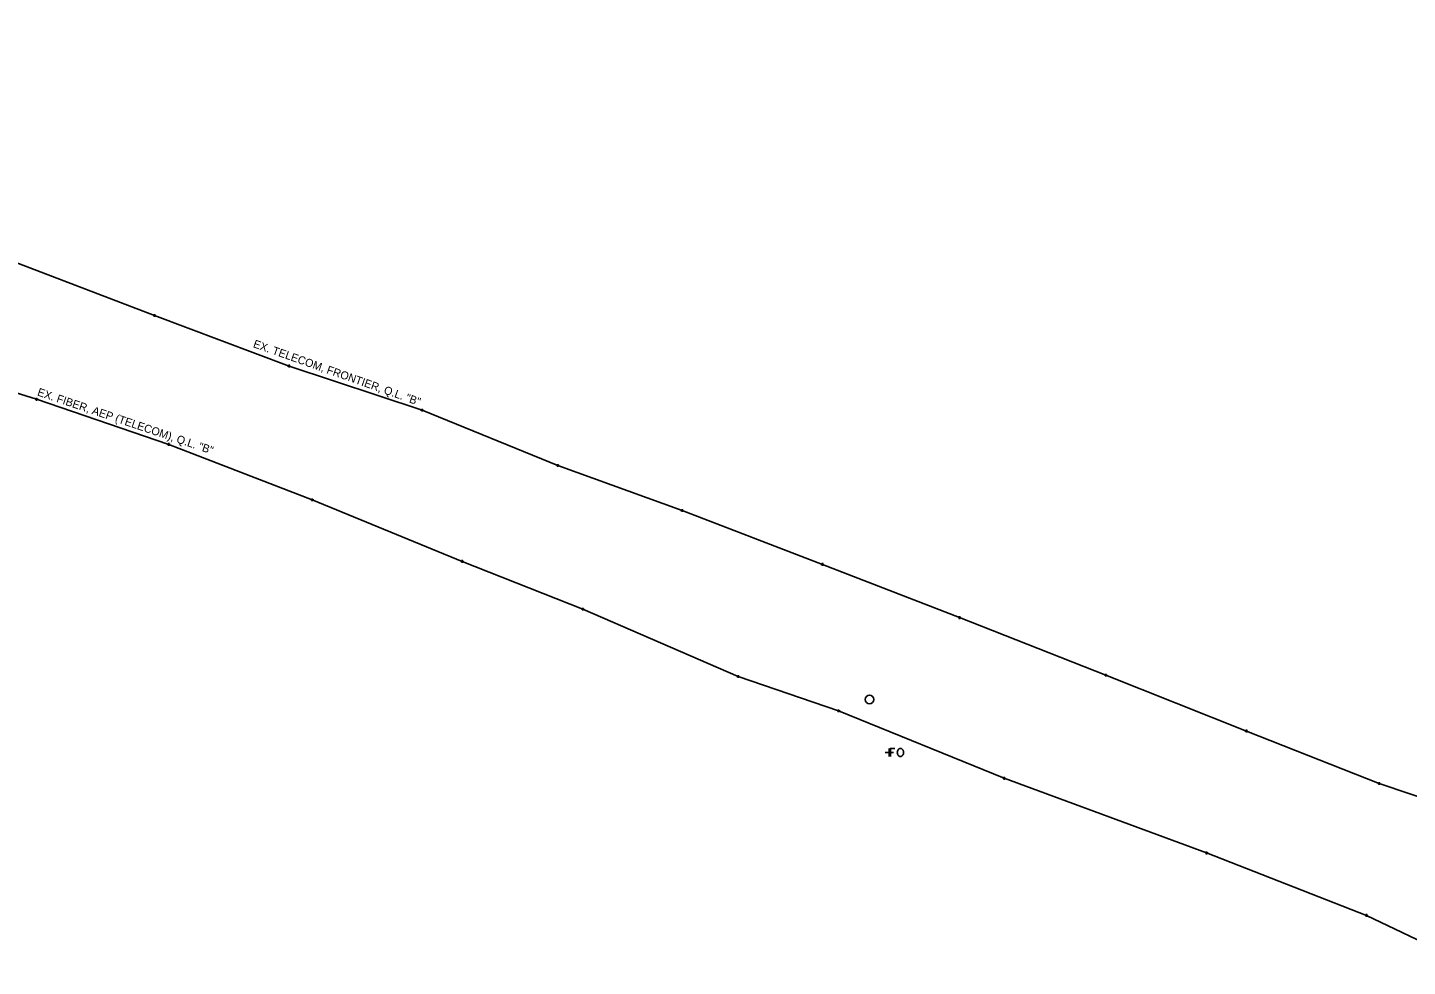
# Model space of a CAD drawing. Extents: x 2046588 to 2048646, y 455919 to 457871.
# Drawn here: x 2047066.7 to 2047549.4, y 456989.8 to 457318.3 of the extents above; entities that cross this region are included whole.
import ezdxf

# ---------------------------------------------------------------- set-up
doc = ezdxf.new("R2010")
doc.units = 0
for name, color, linetype in [('CM_Corridor_Top_Mesh', 7, 'Continuous'), ('MD_P_Surface_Non-Reinforced_Concrete_Pavement', 7, 'Continuous'), ('UT_X_Gas', 7, 'Continuous'), ('UT_X_Gas_Text', 7, 'Continuous'), ('UT_X_Overhead_Combined', 7, 'Continuous'), ('UT_X_Telecom_Text', 7, 'Continuous')]:
    doc.layers.add(name, color=color, linetype=linetype)

msp = doc.modelspace()

# ---------------------------------------------------------------- linework, layer by layer
at = {"layer": 'CM_Corridor_Top_Mesh'}
msp.add_lwpolyline([(2046591.62, 457318.3), (2046634.49, 457314.33), (2046683.6, 457309.26), (2046728.87, 457304.51), (2046756.52, 457301.8), (2046770.98, 457300.11), (2046793.5, 457299.64), (2046823.77, 457296.38), (2046919.05, 457278.1), (2046970.54, 457267.22), (2047006.64, 457256.03), (2047063.52, 457235.76), (2047111.08, 457217.54), (2047158.16, 457199.88), (2047204.68, 457184.45), (2047252.22, 457165.07), (2047295.66, 457149.33), (2047344.75, 457130.49), (2047392.72, 457111.85), (2047443.95, 457091.74), (2047493.09, 457072.16), (2047539.56, 457053.79), (2047583.55, 457039.04), (2047596.82, 457037.26)], dxfattribs=at)
at = {"layer": 'UT_X_Gas'}
for p, q in [((2047110.58, 457217.54), (2047111.58, 457217.54)), ((2047111.08, 457218.04), (2047111.08, 457217.04)), ((2047111.08, 457217.54), (2047111.08, 457217.54)), ((2047157.66, 457199.88), (2047158.66, 457199.88)), ((2047158.16, 457200.38), (2047158.16, 457199.38)), ((2047158.16, 457199.88), (2047158.16, 457199.88)), ((2047069.35, 457188.24), (2047070.35, 457188.24)), ((2047069.85, 457188.74), (2047069.85, 457187.74)), ((2047069.85, 457188.24), (2047069.85, 457188.24)), ((2047204.18, 457184.45), (2047205.18, 457184.45)), ((2047204.68, 457184.95), (2047204.68, 457183.95)), ((2047204.68, 457184.45), (2047204.68, 457184.45)), ((2047115.55, 457172.46), (2047116.55, 457172.46)), ((2047116.05, 457172.96), (2047116.05, 457171.96)), ((2047116.05, 457172.46), (2047116.05, 457172.46)), ((2047252.22, 457165.57), (2047252.22, 457164.57)), ((2047251.72, 457165.07), (2047252.72, 457165.07)), ((2047252.22, 457165.07), (2047252.22, 457165.07)), ((2047165.8, 457153.05), (2047166.8, 457153.05)), ((2047166.3, 457153.55), (2047166.3, 457152.55)), ((2047166.3, 457153.05), (2047166.3, 457153.05)), ((2047295.16, 457149.33), (2047296.16, 457149.33)), ((2047295.66, 457149.83), (2047295.66, 457148.83)), ((2047295.66, 457149.33), (2047295.66, 457149.33)), ((2047218.25, 457131.54), (2047219.25, 457131.54)), ((2047218.75, 457132.04), (2047218.75, 457131.04)), ((2047218.75, 457131.54), (2047218.75, 457131.54)), ((2047344.25, 457130.49), (2047345.25, 457130.49)), ((2047344.75, 457130.99), (2047344.75, 457129.99)), ((2047344.75, 457130.49), (2047344.75, 457130.49)), ((2047260.44, 457114.81), (2047261.44, 457114.81)), ((2047260.94, 457115.31), (2047260.94, 457114.31)), ((2047260.94, 457114.81), (2047260.94, 457114.81)), ((2047392.72, 457112.35), (2047392.72, 457111.35)), ((2047392.22, 457111.85), (2047393.22, 457111.85)), ((2047392.72, 457111.85), (2047392.72, 457111.85)), ((2047314.78, 457091.24), (2047315.78, 457091.24)), ((2047315.28, 457091.74), (2047315.28, 457090.74)), ((2047315.28, 457091.24), (2047315.28, 457091.24)), ((2047443.45, 457091.74), (2047444.45, 457091.74)), ((2047443.95, 457092.24), (2047443.95, 457091.24)), ((2047443.95, 457091.74), (2047443.95, 457091.74)), ((2047349.92, 457079.24), (2047350.92, 457079.24)), ((2047350.42, 457079.74), (2047350.42, 457078.74)), ((2047350.42, 457079.24), (2047350.42, 457079.24)), ((2047492.59, 457072.16), (2047493.59, 457072.16)), ((2047493.09, 457072.66), (2047493.09, 457071.66)), ((2047493.09, 457072.16), (2047493.09, 457072.16)), ((2047407.85, 457055.65), (2047408.85, 457055.65)), ((2047408.35, 457056.15), (2047408.35, 457055.15)), ((2047408.35, 457055.65), (2047408.35, 457055.65)), ((2047539.56, 457054.29), (2047539.56, 457053.29)), ((2047539.06, 457053.79), (2047540.06, 457053.79)), ((2047539.56, 457053.79), (2047539.56, 457053.79)), ((2047479.2, 457030.01), (2047479.2, 457029.01)), ((2047478.7, 457029.51), (2047479.7, 457029.51)), ((2047479.2, 457029.51), (2047479.2, 457029.51)), ((2047534.64, 457007.65), (2047535.64, 457007.65)), ((2047535.14, 457008.15), (2047535.14, 457007.15)), ((2047535.14, 457007.65), (2047535.14, 457007.65))]:
    msp.add_line(p, q, dxfattribs=at)
at = {"layer": 'UT_X_Gas_Text'}
for p, q in [((2047368.15, 457064.67), (2047366.75, 457064.67)), ((2047368.15, 457066.07), (2047368.15, 457063.27)), ((2047368.55, 457064.7), (2047369.63, 457064.7))]:
    msp.add_line(p, q, dxfattribs=at)
for points in [[(2047370.07, 457066.07), (2047368.55, 457066.07), (2047368.55, 457063.27)], [(2047371.84, 457066.05), (2047371.77, 457066.03), (2047371.7, 457066), (2047371.59, 457065.94), (2047371.53, 457065.89), (2047371.42, 457065.81), (2047371.33, 457065.72), (2047371.28, 457065.67), (2047371.22, 457065.59), (2047371.11, 457065.36), (2047371.02, 457065.14), (2047370.98, 457064.95), (2047370.95, 457064.66), (2047370.98, 457064.35), (2047371.04, 457064.13), (2047371.11, 457063.95), (2047371.15, 457063.87), (2047371.22, 457063.76), (2047371.31, 457063.65), (2047371.37, 457063.58), (2047371.44, 457063.51), (2047371.53, 457063.45), (2047371.64, 457063.38), (2047371.84, 457063.29), (2047371.95, 457063.27), (2047372.17, 457063.27), (2047372.25, 457063.29), (2047372.34, 457063.31), (2047372.45, 457063.36), (2047372.56, 457063.42), (2047372.63, 457063.47), (2047372.69, 457063.51), (2047372.76, 457063.58), (2047372.83, 457063.67), (2047372.87, 457063.73), (2047372.92, 457063.8), (2047372.96, 457063.87), (2047373.03, 457064), (2047373.09, 457064.15), (2047373.14, 457064.33), (2047373.16, 457064.48), (2047373.16, 457064.51), (2047373.16, 457064.66), (2047373.16, 457064.79), (2047373.14, 457064.97), (2047373.09, 457065.14), (2047373.05, 457065.28), (2047372.98, 457065.43), (2047372.92, 457065.56), (2047372.81, 457065.7), (2047372.72, 457065.78), (2047372.63, 457065.87), (2047372.54, 457065.94), (2047372.41, 457066), (2047372.28, 457066.05), (2047372.14, 457066.07), (2047371.99, 457066.07), (2047371.84, 457066.05)]]:
    msp.add_lwpolyline(points, dxfattribs=at)
at = {"layer": 'UT_X_Overhead_Combined'}
msp.add_lwpolyline([(2046588.08, 457267.85), (2046613.51, 457265.56), (2046690.46, 457258.74), (2046718.43, 457255.94), (2046763.09, 457251.47), (2046804.41, 457251.19), (2046822.5, 457250.02), (2046854.31, 457243.58), (2046889.51, 457236.2), (2046923.07, 457229.41), (2046962.32, 457220.28), (2046988.27, 457213.7), (2047024.59, 457202.39), (2047069.85, 457188.24), (2047116.05, 457172.46), (2047166.3, 457153.05), (2047218.75, 457131.54), (2047260.94, 457114.81), (2047315.28, 457091.24), (2047350.42, 457079.24), (2047408.35, 457055.65), (2047479.2, 457029.51), (2047535.14, 457007.65), (2047572.61, 456989.81)], dxfattribs=at)
at = {"layer": 'UT_X_Telecom_Text'}
msp.add_circle((2047361.24, 457083.24), 1.5, dxfattribs=at)

# ---------------------------------------------------------------- texts
at = {"layer": 'MD_P_Surface_Non-Reinforced_Concrete_Pavement'}
for s, rotation, p in [('EX. TELECOM, FRONTIER, Q.L. "B"', 340.5139, (2047145.37, 457206.53)), ('EX. FIBER, AEP (TELECOM), Q.L. "B"', 341.3334, (2047069.85, 457189.64))]:
    msp.add_text(s, height=2.8, rotation=rotation, dxfattribs=at).set_placement(p)

doc.saveas('drawing.dxf')
